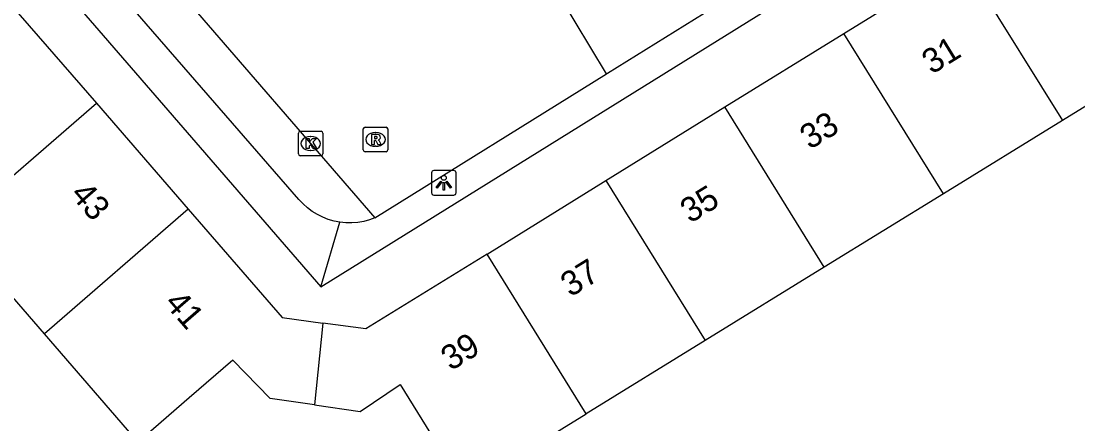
# Model space of a CAD drawing. Extents: x 160304 to 160954, y 383686 to 384161.
# Drawn here: x 160674.85 to 160717.85, y 383982.06 to 383998.44 of the extents above; entities that cross this region are included whole.
import ezdxf

# ---------------------------------------------------------------- set-up
doc = ezdxf.new("R2010")
doc.units = 0
for name, color, linetype in [('IMGEO_Kolk', 7, 'Continuous'), ('IMGEO_Lichtpunt', 7, 'Continuous'), ('IMGEO_Pand', 7, 'Continuous'), ('IMGEO_Pand_nummerreeks', 7, 'Continuous'), ('IMGEO_Rijbaan_lokaal_open', 7, 'Continuous'), ('IMGEO_Rioolput', 7, 'Continuous'), ('IMGEO_Voetpad_open', 7, 'Continuous')]:
    doc.layers.add(name, color=color, linetype=linetype)

msp = doc.modelspace()

# ---------------------------------------------------------------- linework, layer by layer
at = {"layer": 'IMGEO_Kolk'}
for p, q in [((160686.207, 383993.961), (160687.059, 383993.961)), ((160686.132, 383993.035), (160686.132, 383993.887)), ((160686.62, 383993.741), (160686.645, 383993.741)), ((160687.133, 383993.887), (160687.133, 383993.035)), ((160686.643, 383993.181), (160686.618, 383993.181)), ((160687.059, 383992.961), (160686.207, 383992.961))]:
    msp.add_line(p, q, dxfattribs=at)
for points in [[(160686.207, 383993.961), (160687.059, 383993.961)], [(160686.132, 383993.035), (160686.132, 383993.887)], [(160686.453, 383993.661), (160686.576, 383993.661), (160686.576, 383993.51), (160686.706, 383993.661), (160686.87, 383993.661), (160686.724, 383993.51), (160686.877, 383993.261), (160686.725, 383993.261), (160686.64, 383993.425), (160686.576, 383993.358), (160686.576, 383993.261), (160686.453, 383993.261), (160686.453, 383993.661)], [(160687.133, 383993.887), (160687.133, 383993.035)], [(160687.059, 383992.961), (160686.207, 383992.961)]]:
    msp.add_lwpolyline(points, dxfattribs=at)
for centre, start, end in [((160686.209, 383993.885), 91.552, 178.448), ((160686.209, 383993.885), 91.552, 178.448), ((160687.057, 383993.885), 1.552, 88.448), ((160687.057, 383993.885), 1.552, 88.448), ((160686.209, 383993.037), 181.552, 268.448), ((160686.209, 383993.037), 181.552, 268.448), ((160687.057, 383993.037), 271.552, 358.448), ((160687.057, 383993.037), 271.552, 358.448)]:
    msp.add_arc(centre, 0.0765, start, end, dxfattribs=at)
for centre, major_axis, ratio, start_param, end_param in [((160686.619, 383993.461), (-0.387, 0.002), 0.722429, 4.712389, 7.853982), ((160686.644, 383993.461), (-0.39, 0.002), 0.717154, 1.570796, 4.712389)]:
    msp.add_ellipse(centre, major_axis=major_axis, ratio=ratio, start_param=start_param, end_param=end_param, dxfattribs=at)
at = {"layer": 'IMGEO_Lichtpunt'}
for p, q in [((160691.553, 383992.266), (160691.553, 383991.459)), ((160691.553, 383992.266), (160691.553, 383991.459)), ((160692.455, 383992.361), (160691.647, 383992.361)), ((160692.455, 383992.361), (160691.647, 383992.361)), ((160692.549, 383991.459), (160692.549, 383992.266)), ((160692.549, 383991.459), (160692.549, 383992.266)), ((160691.647, 383991.365), (160692.455, 383991.365)), ((160691.647, 383991.365), (160692.455, 383991.365))]:
    msp.add_line(p, q, dxfattribs=at)
for points in [[(160691.927, 383991.93), (160691.966, 383991.902), (160691.778, 383991.64), (160691.74, 383991.667), (160691.927, 383991.93)], [(160692.029, 383991.882), (160692.076, 383991.882), (160692.076, 383991.56), (160692.029, 383991.56), (160692.029, 383991.882)], [(160692.139, 383991.902), (160692.177, 383991.929), (160692.364, 383991.667), (160692.325, 383991.639), (160692.139, 383991.902)]]:
    msp.add_lwpolyline(points, dxfattribs=at)
msp.add_circle((160692.052, 383992.064), 0.0994, dxfattribs=at)
for centre, start, end in [((160691.647, 383992.266), 90, 180), ((160691.647, 383992.266), 90, 180), ((160692.455, 383992.266), 0, 90), ((160692.455, 383992.266), 0, 90), ((160691.647, 383991.459), 180, 270), ((160691.647, 383991.459), 180, 270), ((160692.455, 383991.459), 270, 0), ((160692.455, 383991.459), 270, 360)]:
    msp.add_arc(centre, 0.0946, start, end, dxfattribs=at)
at = {"layer": 'IMGEO_Pand'}
for points in [[(160708.32, 383997.939), (160711.652, 384000), (160713.157, 384000.931)], [(160713.157, 384000.931), (160713.735, 384000), (160717.217, 383994.395)], [(160674.183, 383999.42), (160677.919, 383995.105)], [(160703.483, 383994.947), (160708.32, 383997.939)], [(160712.375, 383991.412), (160708.32, 383997.939)], [(160722.061, 383997.377), (160717.217, 383994.395)], [(160672.065, 383990.036), (160677.919, 383995.105)], [(160677.919, 383995.105), (160681.656, 383990.79)], [(160698.645, 383991.955), (160703.483, 383994.947)], [(160707.531, 383988.43), (160703.483, 383994.947)], [(160717.217, 383994.395), (160712.375, 383991.412)], [(160693.808, 383988.963), (160698.645, 383991.955)], [(160698.645, 383991.955), (160702.687, 383985.447)], [(160712.375, 383991.412), (160707.531, 383988.43)], [(160681.656, 383990.79), (160675.802, 383985.721)], [(160681.656, 383990.79), (160685.47, 383986.384), (160687.13, 383986.157)], [(160675.802, 383985.721), (160672.065, 383990.036)], [(160693.808, 383988.963), (160688.884, 383985.918), (160687.13, 383986.157)], [(160697.845, 383982.465), (160693.808, 383988.963)], [(160707.531, 383988.43), (160702.687, 383985.447)], [(160687.13, 383986.157), (160686.789, 383982.829)], [(160686.789, 383982.829), (160684.992, 383983.088), (160683.471, 383984.653), (160681.691, 383983.111), (160679.618, 383981.315), (160675.802, 383985.721)], [(160702.687, 383985.447), (160697.845, 383982.465)], [(160686.789, 383982.829), (160688.642, 383982.561), (160690.278, 383983.654), (160691.505, 383981.661), (160692.889, 383979.413), (160697.845, 383982.465)]]:
    msp.add_lwpolyline(points, dxfattribs=at)
at = {"layer": 'IMGEO_Rijbaan_lokaal_open'}
for points in [[(160659.582, 384024.746), (160680.98, 384000), (160689.25, 383990.436)], [(160698.671, 383996.302), (160698.705, 383996.323), (160704.611, 384000), (160727.392, 384014.184), (160727.407, 384014.193), (160727.891, 384014.455), (160728.396, 384014.672), (160728.919, 384014.843), (160729.454, 384014.967), (160729.999, 384015.042), (160730.548, 384015.069), (160731.098, 384015.046), (160731.643, 384014.974), (160732.179, 384014.854), (160732.703, 384014.686), (160733.21, 384014.473), (160733.695, 384014.215), (160734.156, 384013.914), (160734.588, 384013.574), (160734.987, 384013.196), (160735.352, 384012.785), (160735.678, 384012.342)], [(160698.671, 383996.302), (160696.125, 384000.545)], [(160689.25, 383990.436), (160698.671, 383996.302)]]:
    msp.add_lwpolyline(points, dxfattribs=at)
at = {"layer": 'IMGEO_Rioolput'}
for p, q in [((160688.773, 383993.202), (160688.773, 383994.054)), ((160688.848, 383994.128), (160689.7, 383994.128)), ((160689.774, 383994.054), (160689.774, 383993.202)), ((160689.261, 383993.908), (160689.286, 383993.908)), ((160689.7, 383993.128), (160688.848, 383993.128)), ((160689.284, 383993.348), (160689.259, 383993.348))]:
    msp.add_line(p, q, dxfattribs=at)
for points in [[(160688.773, 383993.202), (160688.773, 383994.054)], [(160688.848, 383994.128), (160689.7, 383994.128)], [(160689.774, 383994.054), (160689.774, 383993.202)], [(160689.362, 383993.826), (160689.11, 383993.828), (160689.11, 383993.428)], [(160689.11, 383993.428), (160689.234, 383993.428), (160689.234, 383993.59), (160689.245, 383993.59)], [(160689.288, 383993.747), (160689.234, 383993.747), (160689.234, 383993.666)], [(160689.234, 383993.666), (160689.286, 383993.666)], [(160689.292, 383993.561), (160689.363, 383993.428), (160689.503, 383993.428), (160689.438, 383993.554)], [(160689.7, 383993.128), (160688.848, 383993.128)]]:
    msp.add_lwpolyline(points, dxfattribs=at)
for centre, radius, start, end in [((160688.85, 383994.052), 0.0765, 91.552, 178.448), ((160688.85, 383994.052), 0.0765, 91.552, 178.448), ((160689.698, 383994.052), 0.0765, 1.552, 88.448), ((160689.698, 383994.052), 0.0765, 1.552, 88.448), ((160689.244, 383993.537), 0.0533, 26.0293, 88.6989), ((160689.27, 383993.855), 0.19, 274.7715, 282.9687), ((160689.294, 383993.651), 0.0964, 77.0061, 93.1865), ((160689.308, 383993.708), 0.0378, 276.6634, 79.6772), ((160689.361, 383993.716), 0.109, 350.3612, 89.416), ((160689.359, 383993.716), 0.112, 277.5842, 350.9817), ((160689.343, 383993.501), 0.108, 29.5134, 73.7905), ((160688.85, 383993.204), 0.0765, 181.552, 268.448), ((160688.85, 383993.204), 0.0765, 181.552, 268.448), ((160689.698, 383993.204), 0.0765, 271.552, 358.448), ((160689.698, 383993.204), 0.0765, 271.552, 358.448)]:
    msp.add_arc(centre, radius, start, end, dxfattribs=at)
for centre, major_axis, ratio, start_param, end_param in [((160689.26, 383993.628), (-0.387, 0.002), 0.722429, 4.712389, 7.853982), ((160689.285, 383993.628), (-0.39, 0.002), 0.717154, 1.570796, 4.712389)]:
    msp.add_ellipse(centre, major_axis=major_axis, ratio=ratio, start_param=start_param, end_param=end_param, dxfattribs=at)
at = {"layer": 'IMGEO_Voetpad_open'}
for points in [[(160656.955, 384022.413), (160676.351, 384000), (160687.05, 383987.636)], [(160687.824, 383990.261), (160687.585, 383990.307), (160687.352, 383990.375), (160687.125, 383990.462), (160686.907, 383990.57), (160686.7, 383990.697), (160686.504, 383990.841), (160686.322, 383991.003), (160686.156, 383991.18), (160678.508, 384000), (160660.236, 384021.131)], [(160687.05, 383987.636), (160706.936, 384000), (160726.422, 384012.115), (160727.787, 384009.979)], [(160687.05, 383987.636), (160687.824, 383990.261)], [(160689.25, 383990.436), (160689.026, 383990.356), (160688.791, 383990.294), (160688.551, 383990.253), (160688.309, 383990.234), (160688.066, 383990.237), (160687.824, 383990.261)]]:
    msp.add_lwpolyline(points, dxfattribs=at)

# ---------------------------------------------------------------- texts
at = {"layer": 'IMGEO_Pand_nummerreeks'}
for s, rotation, p in [('31', 31.6422, (160711.905, 383996.252)), ('33', 31.6422, (160706.941, 383993.192)), ('43', 310.8767, (160676.816, 383991.37)), ('35', 31.6422, (160702.072, 383990.192)), ('37', 31.6422, (160697.204, 383987.192)), ('41', 310.8746, (160680.646, 383986.947)), ('39', 31.6445, (160692.336, 383984.191))]:
    msp.add_text(s, height=1, rotation=rotation, dxfattribs=at).set_placement(p)

doc.saveas('drawing.dxf')
